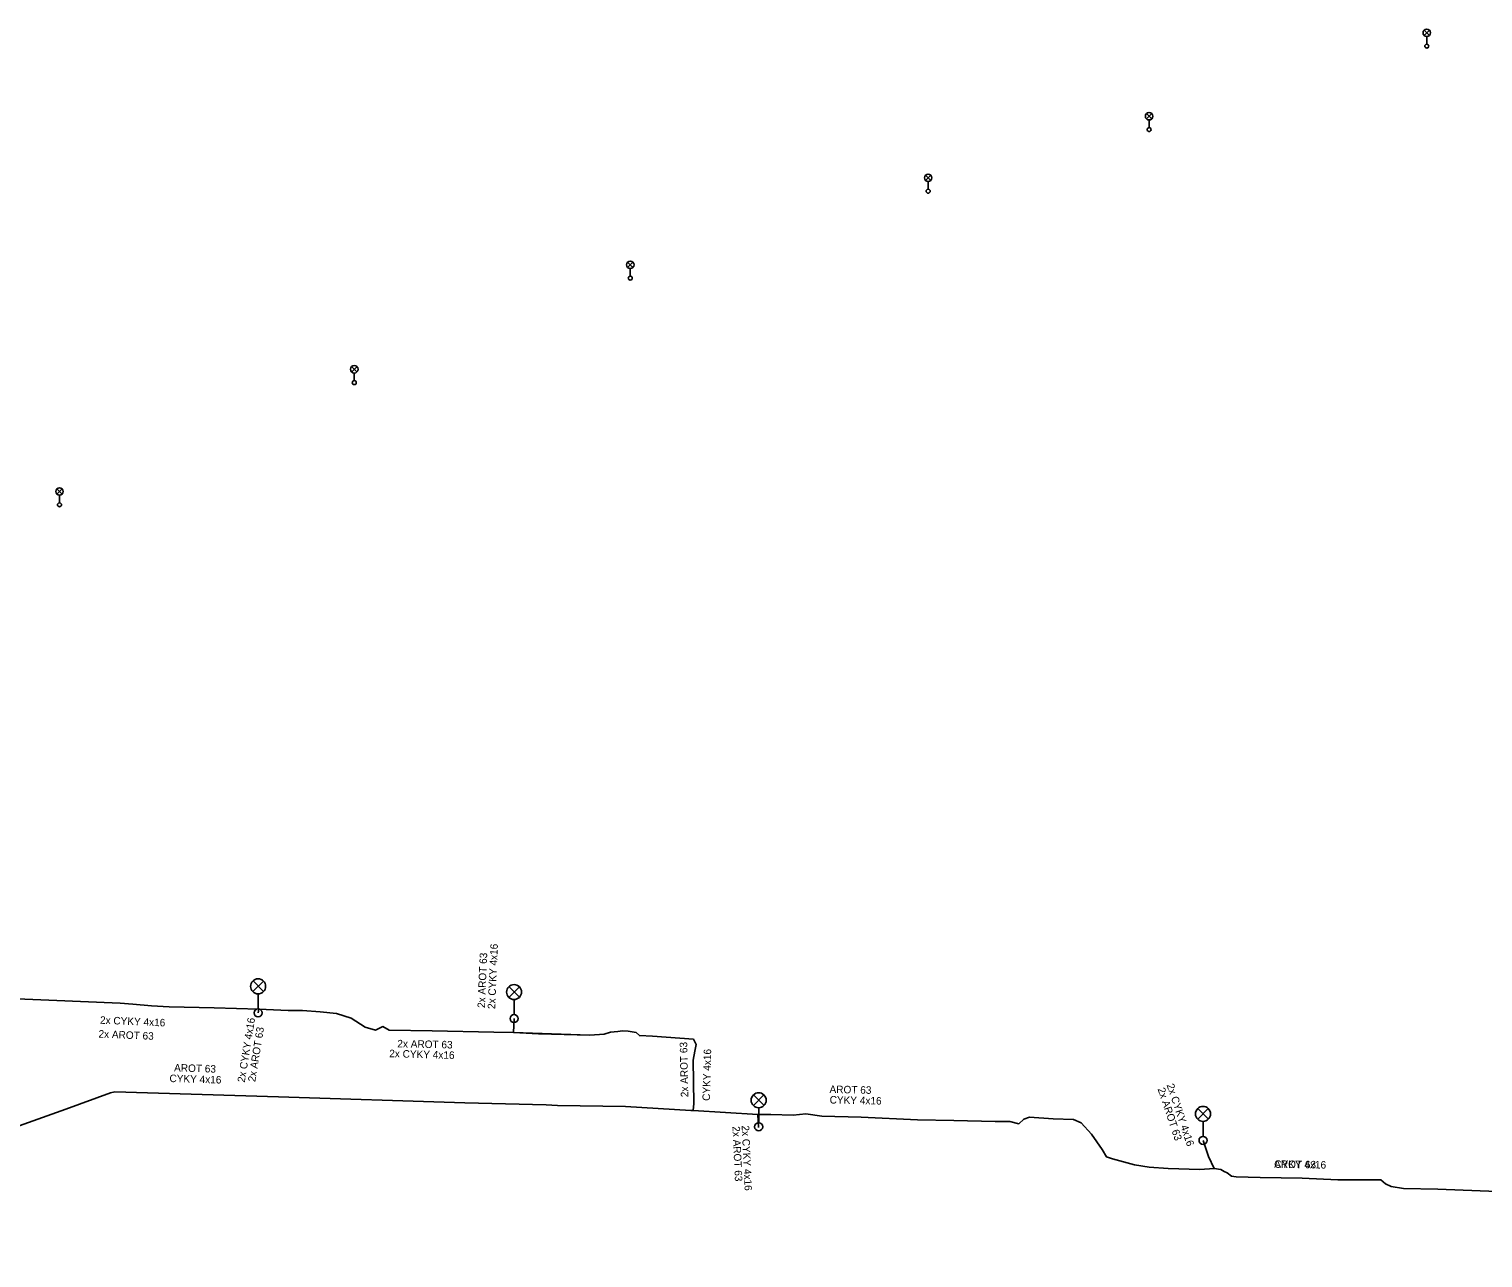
# Model space of a CAD drawing. Extents: x -641884 to -641258, y -1196509 to -1195931.
# Drawn here: x -641713.6 to -641568.4, y -1196064.6 to -1195942 of the extents above; entities that cross this region are included whole.
import ezdxf

# ---------------------------------------------------------------- set-up
doc = ezdxf.new("R2010")
doc.units = 0
for name, color, linetype in [('TECH_OCHR_PÁSMO_HRAN', 7, 'Continuous'), ('Vrstva 22', 7, 'Continuous'), ('Vrstva 31', 7, 'Continuous'), ('ZP_EON', 7, 'Continuous'), ('ZP_EON_POPIS', 7, 'Continuous')]:
    doc.layers.add(name, color=color, linetype=linetype)

msp = doc.modelspace()

# ---------------------------------------------------------------- linework, layer by layer
at = {"layer": 'TECH_OCHR_PÁSMO_HRAN'}
for p, q in [((-641690.64, -1196039.81), (-641690.7, -1196040.18)), ((-641665.21, -1196042.15), (-641665.15, -1196040.75)), ((-641640.82, -1196050.33), (-641640.76, -1196051.62))]:
    msp.add_line(p, q, dxfattribs=at)
for points in [[(-641719.39, -1196038.48), (-641717.98, -1196038.63), (-641711.58, -1196038.92), (-641704.47, -1196039.22), (-641703.2, -1196039.32), (-641701.33, -1196039.49), (-641699.59, -1196039.56), (-641695.1, -1196039.67), (-641690.64, -1196039.81)], [(-641690.64, -1196039.81), (-641687.7, -1196039.94), (-641686.27, -1196039.93), (-641684.51, -1196040.06), (-641682.88, -1196040.24), (-641681.41, -1196040.71), (-641680.02, -1196041.61), (-641678.98, -1196041.89), (-641678.26, -1196041.54), (-641677.62, -1196041.89), (-641673.34, -1196041.98), (-641667.17, -1196042.11), (-641665.21, -1196042.15), (-641657.6, -1196042.41), (-641656.14, -1196042.3), (-641655.51, -1196042.11), (-641654.8, -1196042.03), (-641654.31, -1196041.96), (-641653.75, -1196042.01), (-641652.96, -1196042.14), (-641652.63, -1196042.44), (-641651.34, -1196042.5), (-641647.25, -1196042.8), (-641646.96, -1196043.35), (-641647.09, -1196044.01), (-641647.26, -1196044.91), (-641647.2, -1196049.23), (-641647.27, -1196049.94)], [(-641647.27, -1196049.94), (-641647.5, -1196049.92), (-641654.02, -1196049.51), (-641660.8, -1196049.42), (-641661.95, -1196049.35), (-641670.08, -1196049.16), (-641688.67, -1196048.56), (-641704.99, -1196048.06), (-641705.44, -1196048.15), (-641709.91, -1196049.79), (-641714.57, -1196051.44), (-641716.59, -1196052.24), (-641718.25, -1196052.73), (-641719.93, -1196053.33), (-641725.48, -1196056.34), (-641728.46, -1196057.54), (-641736.62, -1196062.62), (-641737.5, -1196063.15), (-641738.36, -1196063.61), (-641739.31, -1196064.06), (-641740.32, -1196064.64)], [(-641640.82, -1196050.33), (-641647.27, -1196049.94)], [(-641595.26, -1196055.7), (-641596.68, -1196055.81), (-641599.86, -1196055.7), (-641601.73, -1196055.57), (-641603.21, -1196055.36), (-641605.42, -1196054.75), (-641606.01, -1196054.54), (-641606.45, -1196053.83), (-641607.5, -1196052.29), (-641608.52, -1196051.15), (-641609.31, -1196050.81), (-641611.34, -1196050.76), (-641613.7, -1196050.59), (-641614.25, -1196050.78), (-641614.76, -1196051.24), (-641615.64, -1196051.03), (-641617.13, -1196051.02), (-641621.24, -1196050.92), (-641624.89, -1196050.86), (-641630.51, -1196050.59), (-641634.44, -1196050.5), (-641636.02, -1196050.27), (-641637.27, -1196050.38), (-641639.5, -1196050.33), (-641640.82, -1196050.33)], [(-641595.26, -1196055.7), (-641595.83, -1196054.52), (-641596.37, -1196052.91)], [(-641559.21, -1196058.31), (-641560.06, -1196058.22), (-641567.01, -1196058.01), (-641572.92, -1196057.79), (-641576.36, -1196057.7), (-641577.6, -1196057.52), (-641578.14, -1196057.25), (-641578.63, -1196056.85), (-641580.93, -1196056.84), (-641582.91, -1196056.85), (-641586.46, -1196056.69), (-641590.66, -1196056.62), (-641593.07, -1196056.55), (-641593.52, -1196056.48), (-641593.96, -1196056.13), (-641594.25, -1196056), (-641594.6, -1196055.82), (-641595.26, -1196055.7)]]:
    msp.add_lwpolyline(points, dxfattribs=at)
at = {"layer": 'Vrstva 31'}
for p, q in [((-641574.29, -1195942.61), (-641573.77, -1195942.08)), ((-641573.76, -1195942.6), (-641574.29, -1195942.08)), ((-641574.03, -1195942.72), (-641574.03, -1195943.47)), ((-641602.01, -1195950.94), (-641601.49, -1195950.41)), ((-641601.48, -1195950.93), (-641602.01, -1195950.41)), ((-641601.75, -1195951.05), (-641601.75, -1195951.8)), ((-641624.07, -1195957.09), (-641623.55, -1195956.56)), ((-641623.54, -1195957.08), (-641624.07, -1195956.56)), ((-641623.81, -1195957.2), (-641623.81, -1195957.95)), ((-641653.81, -1195965.77), (-641653.29, -1195965.24)), ((-641653.28, -1195965.76), (-641653.81, -1195965.24)), ((-641653.55, -1195965.88), (-641653.55, -1195966.63)), ((-641681.36, -1195976.2), (-641680.84, -1195975.67)), ((-641680.83, -1195976.19), (-641681.36, -1195975.67)), ((-641681.1, -1195976.31), (-641681.1, -1195977.06)), ((-641710.79, -1195988.4), (-641710.27, -1195987.87)), ((-641710.26, -1195988.39), (-641710.79, -1195987.87)), ((-641710.53, -1195988.51), (-641710.53, -1195989.26)), ((-641691.23, -1196038.06), (-641690.17, -1196037)), ((-641690.16, -1196038.05), (-641691.21, -1196036.99)), ((-641665.68, -1196038.63), (-641664.62, -1196037.57)), ((-641664.61, -1196038.62), (-641665.66, -1196037.56)), ((-641690.7, -1196038.28), (-641690.7, -1196039.78)), ((-641665.15, -1196038.85), (-641665.15, -1196040.35)), ((-641641.26, -1196049.43), (-641640.2, -1196048.37)), ((-641640.19, -1196049.42), (-641641.24, -1196048.36)), ((-641640.73, -1196049.65), (-641640.73, -1196051.15)), ((-641596.9, -1196050.79), (-641595.84, -1196049.73)), ((-641595.83, -1196050.78), (-641596.88, -1196049.72)), ((-641596.37, -1196051.01), (-641596.37, -1196052.51))]:
    msp.add_line(p, q, dxfattribs=at)
for centre, radius in [((-641574.03, -1195942.34), 0.375), ((-641574.03, -1195943.67), 0.2), ((-641601.75, -1195950.67), 0.375), ((-641601.75, -1195952), 0.2), ((-641623.81, -1195956.82), 0.375), ((-641623.81, -1195958.15), 0.2), ((-641653.55, -1195965.5), 0.375), ((-641653.55, -1195966.83), 0.2), ((-641681.1, -1195975.93), 0.375), ((-641681.1, -1195977.26), 0.2), ((-641710.53, -1195988.13), 0.375), ((-641710.53, -1195989.46), 0.2), ((-641690.7, -1196037.53), 0.75), ((-641665.15, -1196038.1), 0.75), ((-641690.7, -1196040.18), 0.4), ((-641665.15, -1196040.75), 0.4), ((-641640.73, -1196048.9), 0.75), ((-641596.37, -1196050.26), 0.75), ((-641640.73, -1196051.55), 0.4), ((-641596.37, -1196052.91), 0.4)]:
    msp.add_circle(centre, radius, dxfattribs=at)
at = {"layer": 'ZP_EON'}
for p, q in [((-641690.64, -1196039.81), (-641690.7, -1196040.18)), ((-641665.21, -1196042.15), (-641665.15, -1196040.75)), ((-641640.82, -1196050.33), (-641640.76, -1196051.62))]:
    msp.add_line(p, q, dxfattribs=at)
for points in [[(-641719.39, -1196038.48), (-641717.98, -1196038.63), (-641711.58, -1196038.92), (-641704.47, -1196039.22), (-641703.2, -1196039.32), (-641701.33, -1196039.49), (-641699.59, -1196039.56), (-641695.1, -1196039.67), (-641690.64, -1196039.81)], [(-641690.64, -1196039.81), (-641687.7, -1196039.94), (-641686.27, -1196039.93), (-641684.51, -1196040.06), (-641682.88, -1196040.24), (-641681.41, -1196040.71), (-641680.02, -1196041.61), (-641678.98, -1196041.89), (-641678.26, -1196041.54), (-641677.62, -1196041.89), (-641673.34, -1196041.98), (-641667.17, -1196042.11), (-641665.21, -1196042.15)], [(-641665.21, -1196042.15), (-641662.72, -1196042.27), (-641657.6, -1196042.41), (-641656.14, -1196042.3), (-641655.51, -1196042.11), (-641654.8, -1196042.03), (-641654.31, -1196041.96), (-641653.75, -1196042.01), (-641652.96, -1196042.14), (-641652.63, -1196042.44), (-641651.34, -1196042.5), (-641647.25, -1196042.8), (-641646.96, -1196043.35), (-641647.09, -1196044.01), (-641647.26, -1196044.91), (-641647.2, -1196049.23), (-641647.27, -1196049.94)], [(-641647.27, -1196049.94), (-641647.5, -1196049.92), (-641654.02, -1196049.51), (-641660.8, -1196049.42), (-641661.95, -1196049.35), (-641670.08, -1196049.16), (-641688.67, -1196048.56), (-641704.99, -1196048.06), (-641705.44, -1196048.15), (-641709.91, -1196049.79), (-641714.57, -1196051.44), (-641716.59, -1196052.24), (-641718.25, -1196052.73), (-641719.93, -1196053.33), (-641725.48, -1196056.34), (-641728.46, -1196057.54), (-641736.62, -1196062.62), (-641737.5, -1196063.15), (-641738.36, -1196063.61), (-641739.31, -1196064.06), (-641740.32, -1196064.64)], [(-641640.82, -1196050.33), (-641647.27, -1196049.94)], [(-641595.26, -1196055.7), (-641596.68, -1196055.81), (-641599.86, -1196055.7), (-641601.73, -1196055.57), (-641603.21, -1196055.36), (-641605.42, -1196054.75), (-641606.01, -1196054.54), (-641606.45, -1196053.83), (-641607.5, -1196052.29), (-641608.52, -1196051.15), (-641609.31, -1196050.81), (-641611.34, -1196050.76), (-641613.7, -1196050.59), (-641614.25, -1196050.78), (-641614.76, -1196051.24), (-641615.64, -1196051.03), (-641617.13, -1196051.02), (-641621.24, -1196050.92), (-641624.89, -1196050.86), (-641630.51, -1196050.59), (-641634.44, -1196050.5), (-641636.02, -1196050.27), (-641637.27, -1196050.38), (-641639.5, -1196050.33), (-641640.82, -1196050.33)], [(-641595.26, -1196055.7), (-641595.83, -1196054.52), (-641596.37, -1196052.91)], [(-641559.21, -1196058.31), (-641560.06, -1196058.22), (-641567.01, -1196058.01), (-641572.92, -1196057.79), (-641576.36, -1196057.7), (-641577.6, -1196057.52), (-641578.14, -1196057.25), (-641578.63, -1196056.85), (-641580.93, -1196056.84), (-641582.91, -1196056.85), (-641586.46, -1196056.69), (-641590.66, -1196056.62), (-641593.07, -1196056.55), (-641593.52, -1196056.48), (-641593.96, -1196056.13), (-641594.25, -1196056), (-641594.6, -1196055.82), (-641595.26, -1196055.7)]]:
    msp.add_lwpolyline(points, dxfattribs=at)

# ---------------------------------------------------------------- texts
at = {"layer": 'Vrstva 22'}
for s, rotation, p in [('2x AROT 63', 87.546, (-641668.06, -1196039.7)), ('2x AROT 63', 357.5839, (-641706.65, -1196042.64)), ('2x AROT 63', 80.789, (-641690.99, -1196047.1)), ('2x AROT 63', 358.7954, (-641676.81, -1196043.62)), ('2x AROT 63', 91.1973, (-641647.75, -1196048.59)), ('AROT 63', 358.2452, (-641699.1, -1196046.02)), ('AROT 63', 358.6881, (-641633.66, -1196048.17)), ('2x AROT 63', 288.5416, (-641600.91, -1196047.78)), ('2x AROT 63', 272.663, (-641643.35, -1196051.51)), ('AROT 63', 359.0452, (-641589.27, -1196055.64))]:
    msp.add_text(s, height=0.75, rotation=rotation, dxfattribs=at).set_placement(p)
at = {"layer": 'ZP_EON_POPIS'}
for s, rotation, p in [('2x CYKY 4x16', 87.546, (-641667.04, -1196039.81)), ('2x CYKY 4x16', 357.5839, (-641706.5, -1196041.26)), ('2x CYKY 4x16', 80.789, (-641692.04, -1196047.16)), ('2x CYKY 4x16', 358.3994, (-641677.62, -1196044.6)), ('CYKY 4x16', 88.4894, (-641645.6, -1196048.97)), ('CYKY 4x16', 358.2452, (-641699.56, -1196047.08)), ('2x CYKY 4x16', 288.5416, (-641600.01, -1196047.38)), ('CYKY 4x16', 358.6881, (-641633.65, -1196049.22)), ('2x CYKY 4x16', 272.663, (-641642.43, -1196051.43)), ('CYKY 4x16', 359.0452, (-641589.27, -1196055.64))]:
    msp.add_text(s, height=0.75, rotation=rotation, dxfattribs=at).set_placement(p)

doc.saveas('drawing.dxf')
